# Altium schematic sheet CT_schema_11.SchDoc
size 281 x 153 mm
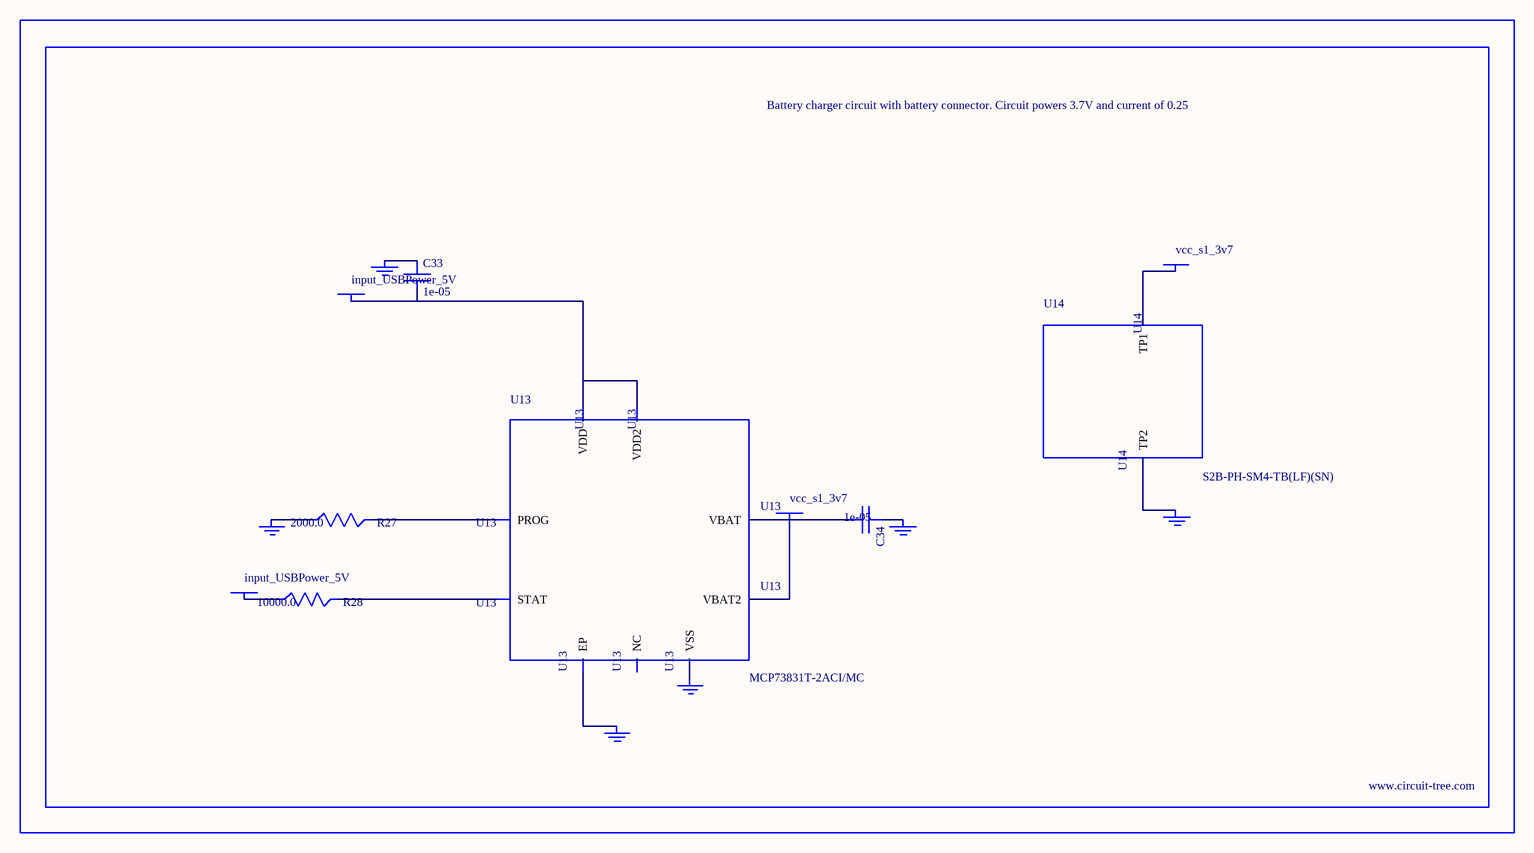
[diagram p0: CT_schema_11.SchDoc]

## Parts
BORDER10  (no value)
C33  1e-05  [C1206]
C34  1e-05  [C1206]
GND_INSTANCE_10_0  (no value)
GND_INSTANCE_10_1  (no value)
GND_INSTANCE_10_2  (no value)
GND_INSTANCE_10_3  (no value)
GND_INSTANCE_10_4  (no value)
GND_INSTANCE_10_5  (no value)
POWER_INSTANCE_10_0  input_USBPower_5V
POWER_INSTANCE_10_1  input_USBPower_5V
POWER_INSTANCE_10_2  vcc_s1_3v7
POWER_INSTANCE_10_3  vcc_s1_3v7
R27  2000.0  [R0603]
R28  10000.0  [R0603]
U13  MCP73831T-2ACI/MC  [DFN8_2X3MC]
U14  S2B-PH-SM4-TB(LF)(SN)  [JST-2-SMD]

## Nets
NetC33_1: C33.1 GND_INSTANCE_10_0.0(GND)
NetC33_2: C33.2 POWER_INSTANCE_10_0.0(PWR) U13.1(VDD) U13.2(VDD2)
NetC34_1: C34.1 GND_INSTANCE_10_1.0(GND)
NetC34_2: C34.2 POWER_INSTANCE_10_2.0(PWR) U13.3(VBAT) U13.4(VBAT2)
NetGND_INSTANCE_10_2_0: GND_INSTANCE_10_2.0(GND) R27.1
NetGND_INSTANCE_10_3_0: GND_INSTANCE_10_3.0(GND) U13.9(EP)
NetGND_INSTANCE_10_4_0: GND_INSTANCE_10_4.0(GND) U13.6(VSS)
NetGND_INSTANCE_10_5_0: GND_INSTANCE_10_5.0(GND) U14.2(TP2)
NetPOWER_INSTANCE_10_1_0: POWER_INSTANCE_10_1.0(PWR) R28.1
NetPOWER_INSTANCE_10_3_0: POWER_INSTANCE_10_3.0(PWR) U14.1(TP1)
NetR27_2: R27.2 U13.8(PROG)
NetR28_2: R28.2 U13.5(STAT)

Not connected (* = marked no-connect by the designer): U13 7(NC)

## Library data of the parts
BORDER10 = BORDER_PAGE10
C33 C34 = C1206C106K3RACTU
GND_INSTANCE_10_0-GND_INSTANCE_10_5 = GND
POWER_INSTANCE_10_0-POWER_INSTANCE_10_3 = PWR
R27 = RC0603JR-072KL
R28 = RC0603JR-0710KL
